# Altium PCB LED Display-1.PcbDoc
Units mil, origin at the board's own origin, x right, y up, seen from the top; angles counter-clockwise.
Board outline 2585 x 1955 mil, 2 copper layers (Top Layer, Bottom Layer); 14 components, 34 nets, 125 pads, 30 vias.
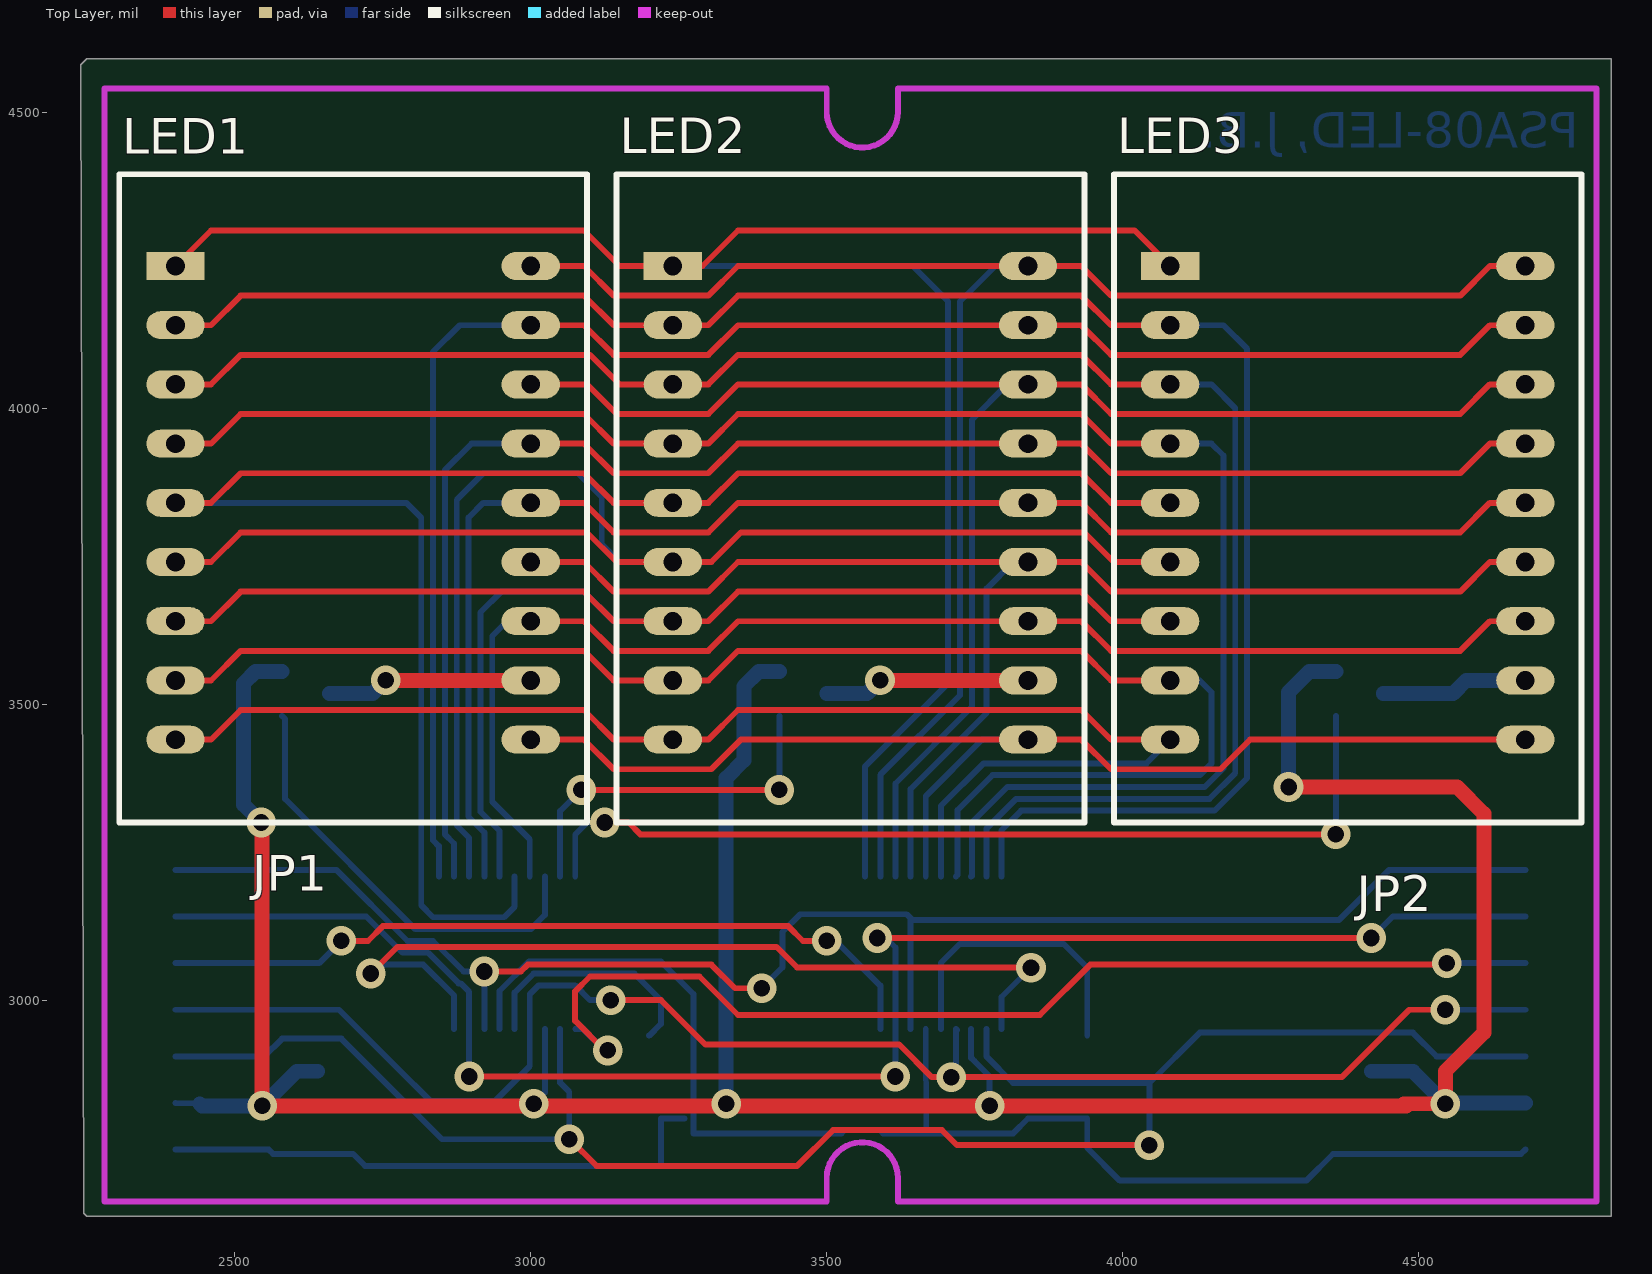
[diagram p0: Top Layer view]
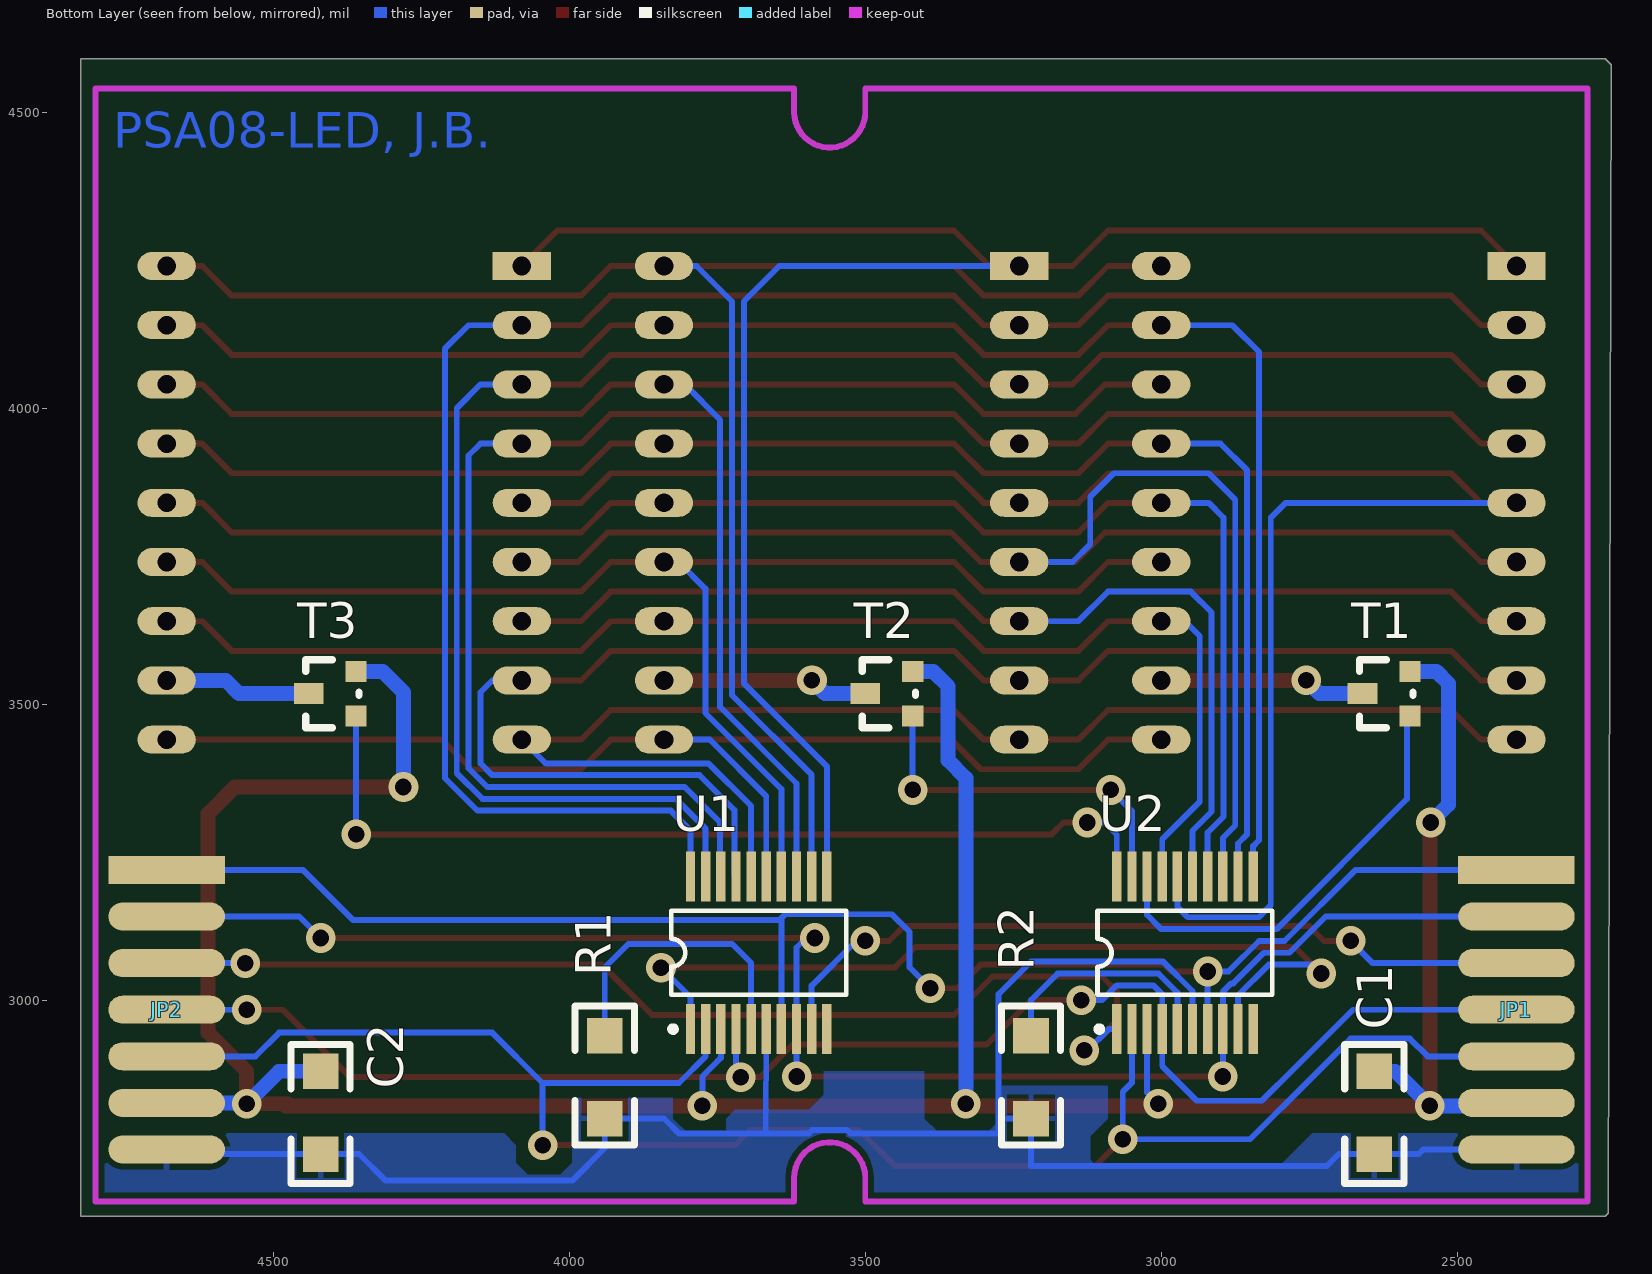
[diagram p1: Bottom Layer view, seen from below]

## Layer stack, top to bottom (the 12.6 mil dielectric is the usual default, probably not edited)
Top Layer: signal copper 1.4
Dielectric: dielectric 12.6, FR-4, Dk 4.8
Bottom Layer: signal copper 1.4

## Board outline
2240,4580 2250,4590 4825,4590 4825,2635 2250,2635 2245,2640

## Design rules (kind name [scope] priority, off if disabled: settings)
Clearance [All] p1: gap=10
PolygonConnect [All] p1: connectstyle=Relief reliefconductorwidth=10 reliefentries=4 polygonreliefangle="90 Angle"
RoutingVias [All] p1: holewidth=28 width=50 viastyle="Through Hole" minholewidth=28 minwidth=50 maxholewidth=28 maxwidth=50
SilkscreenOverComponentPads [All] p1: minsilkscreentomaskgap=10
SolderMaskExpansion [All] p1: expansion=4
Width [All] p1: maxlimit=50 minlimit=10 preferedwidth=10
27 further rules are at their usual default settings.

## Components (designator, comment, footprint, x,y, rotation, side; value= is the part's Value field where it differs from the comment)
C1 "Cap" 1206 2640,2740 r90 bottom
C2 "Cap" 1206 4420,2740 r90 bottom
JP1 "Header 7" ZLACZE-K7 2400,3220 r270 top
JP2 "Header 7" ZLACZE-K7 4680,3220 r270 top
LED1 "PSA11-08GWA" PSA08-11 2400,4240 r0 top
LED2 "PSA11-08GWA" PSA08-11 3240,4240 r0 top
LED3 "PSA11-08GWA" PSA08-11 4080,4240 r0 top
R1 "Res2" 1206 3940,2940 r270 bottom
R2 "Res2" 1206 3220,2940 r270 bottom
T1 "BC858B" SOT-23 2580,3480 r90 bottom
T2 "BC858B" SOT-23 3420,3480 r90 bottom
T3 "BC858B" SOT-23 4360,3480 r90 bottom
U1 "PR4010" SSOP20 3680,3080 r180 bottom
U2 "PR4010" SSOP20 2960,3080 r180 bottom

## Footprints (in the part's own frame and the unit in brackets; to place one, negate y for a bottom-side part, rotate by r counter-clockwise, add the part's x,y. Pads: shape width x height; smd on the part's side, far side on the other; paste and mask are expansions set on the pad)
1206 [mil]
  rect 60x60 smd: 1(0,0) 2(140,0)
  silkscreen extent -50,-50 185,50
PSA08-11 [mm]
  rect 2.5x1.2 hole 0.8: 1(0,0)
  oval 2.5x1.2 hole 0.8: 2(0,-2.54) 3(0,-5.08) 4(0,-7.62) 5(0,-10.16) 6(0,-12.7) 7(0,-15.24) 8(0,-17.78) 9(0,-20.32) 10(15.24,-20.32) 11(15.24,-17.78) 12(15.24,-15.24) 13(15.24,-12.7) 14(15.24,-10.16) 15(15.24,-7.62) 16(15.24,-5.08) 17(15.24,-2.54) 18(15.24,0)
  silkscreen extent -2.41,-23.88 17.65,3.94
SOT-23 [mil]
  rect 36x36 smd: 1(0,0) 2(75,0)
  rect 36x50 smd: 3(38,80)
  silkscreen extent -20,-5 95,85
SSOP20 [mm] "SSOP, Plastic; 20 Leads; Body Width 5.3 mm; Pitch 0.65 mm"
  rect 0.4x2.15 smd: 1(-2.925,-3.275) 2(-2.275,-3.275) 3(-1.625,-3.275) 4(-0.975,-3.275) 5(-0.325,-3.275) 6(0.325,-3.275) 7(0.975,-3.275) 8(1.625,-3.275) 9(2.275,-3.275) 10(2.925,-3.275) 11(2.925,3.275) 12(2.275,3.275) 13(1.625,3.275) 14(0.975,3.275) 15(0.325,3.275) 16(-0.325,3.275) 17(-0.975,3.275) 18(-1.625,3.275) 19(-2.275,3.275) 20(-2.925,3.275)
  silkscreen extent -3.8,-3.4 3.75,1.8
ZLACZE-K7 [mm]
  rect 1.2x5 smd far side: 1(0,0)
  oval 1.2x5 smd far side: 2(2,0) 3(4,0) 4(6,0) 5(8,0) 6(10,0) 7(12,0)

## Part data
C1 C2: "Capacitor"
JP1 JP2: "Header, 7-Pin"
R1 R2: "Resistor"
T1 T2 T3: library part PNP, "PNP Bipolar Transistor"

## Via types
v1: diameter 50, hole 28, Top Layer to Bottom Layer, 30 vias

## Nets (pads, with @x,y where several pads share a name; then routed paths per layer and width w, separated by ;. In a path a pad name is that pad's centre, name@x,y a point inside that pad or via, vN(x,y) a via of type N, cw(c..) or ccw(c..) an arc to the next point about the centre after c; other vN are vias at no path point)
DIG1: T1.1 U2.18 | length 747.1
  Bottom Layer w10: T1.1 2585,3475 2585,3340 2805,3120 3000,3120 3023.98,3143.98 U2.18
DIG2: T2.1 U2.19 | length 620.7
  Top Layer w10: v1(3085,3355) v1(3420,3355)
  Bottom Layer w10: U2.19 3049.57,3319.57 v1(3085,3355) ; v1(3420,3355) T2.1
DIG3: T3.1 U2.20 | length 1572.4
  Top Layer w10: v1(3125,3300) 3165,3300 3185,3280 v1(4360,3280)
  Bottom Layer w10: U2.20 3075.16,3279.84 3095.32,3300 v1(3125,3300) ; v1(4360,3280) T3.1
GND: C1.1 C2.1 JP1.7 JP2.7 R1.2 R2.2 U1.6 U2.6 | length 3312.5
  Bottom Layer w10: JP1.7 2557.44,2747.56 2565,2740 C1.1 2700,2740 2720,2720 3220,2720 R2.2 3260,2800 ; U2.6 2947.2,3015.49 2996.72,3065 3220,3065 3275,3010 3275,2775 3524.78,2775 3530.47,2780.69 3589.53,2780.69 3595.22,2775 3735,2775 3815,2775 3840,2800 R1.2 3940,2750.12 3995.12,2695 4310,2695 4355,2740 4672.44,2740 JP2.7 ; U1.6 3668,2775
NetJP1_1: JP1.1 JP2.1 U1.7 U2.7 | length 2783.4
  Top Layer w10: v1(2921.61,3048.39) 2983.39,3048.39 2995,3060 3305,3060 3345,3020 v1(3390,3020)
  Bottom Layer w10: JP1.1 2671.72,3220 2791.72,3100 2835,3100 2886.61,3048.39 v1(2921.61,3048.39) U2.7 ; v1(3390,3020) 3425,3055 3425,3115 3455,3145 3635,3145 3645,3135 4365,3135 4450,3220 JP2.1 ; U1.7 3641.61,3138.39
NetJP1_2: JP1.2 JP2.2 U1.8 U2.8 | length 2777.3
  Top Layer w10: v1(2896.02,2871.02) v1(3616.02,2871.02) ; v1(3585,3105) v1(4420,3105)
  Bottom Layer w10: JP1.2 2722.17,3141.26 2783.43,3080 2826.72,3080 2878.33,3028.39 2881.61,3028.39 2896.02,3013.98 U2.8 v1(2896.02,2871.02) ; v1(3585,3105) 3600,3105 3616.02,3088.98 U1.8 v1(3616.02,2871.02) ; v1(4420,3105) 4456.26,3141.26 JP2.2
NetJP1_3: JP1.3 U1.9 | length 1331.4
  Top Layer w10: v1(2680,3100) 2725,3100 2750,3125 3330,3125 3435,3125 3460,3100 v1(3500,3100)
  Bottom Layer w10: JP1.3 2642.52,3062.52 v1(2680,3100) ; v1(3500,3100) 3515,3100 3590.43,3024.57 U1.9
NetJP1_4: JP1.4 JP2.4 U1.4 U2.4 | length 2693.9
  Top Layer w10: v1(3135,3000) 3220,3000 3295,2925 3622.2,2925 3677.2,2870 3687.2,2870 v1(3710,2870) 4370,2870 4483.78,2983.78 v1(4545,2983.78)
  Bottom Layer w10: JP1.4 2676.22,2983.78 2775,2885 2830,2830 2940,2830 2998.39,2888.39 U2.4 2998.39,3010.1 3013.28,3025 3075,3025 3100,3000 v1(3135,3000) ; v1(3710,2870) 3718.39,2878.39 U1.4 U1.4@3720,2949.45 ; v1(4545,2983.78) JP2.4
NetJP1_5: JP1.5 JP2.5 U1.2 U2.2 | length 3106.6
  Top Layer w10: v1(3065,2765) 3065.95,2765 3110.95,2720 3450,2720 3510.69,2780.69 3694.31,2780.69 3720,2755 v1(4045,2755)
  Bottom Layer w10: JP1.5 2550.04,2905.04 2580,2935 2680,2935 2745,2870 2850,2765 v1(3065,2765) 3065,2845 3049.57,2860.43 U2.2 ; U1.2 3769.57,2905 3814.57,2860 4045,2860 ; v1(4045,2755) 4045,2860 ; JP2.5 4529.96,2905.04 4490,2945 4130,2945 4045,2860
NetJP2_3: JP2.3 U2.1 | length 1870.5
  Top Layer w10: v1(3130,2915) 3125,2915 3075,2965 3075,3015 3100,3040 3285,3040 3350,2975 3860,2975 3945,3060 v1@4545,3060
  Bottom Layer w10: U2.1 3088.94,2951.06 3125,2915 v1(3130,2915) ; v1(4547.52,3062.52) JP2.3
NetLED1_11: LED1.11 T1.3 | length 349.1
  Top Layer w25: v1(2755,3540) LED1.11
  Bottom Layer w25: T1.3 2733,3518 v1(2755,3540)
NetLED2_11: LED2.11 T2.3 | length 349.1
  Top Layer w25: v1(3590,3540) LED2.11
  Bottom Layer w25: T2.3 3568,3518 v1(3590,3540)
NetLED3_11: LED3.11 T3.3 | length 249.1
  Bottom Layer w25: T3.3 4558,3518 4580,3540 LED3.11
NetR1_1: R1.1 U1.5 | length 503.8
  Bottom Layer w10: U1.5 3692.8,3062.8 3725,3095 3828.43,3095 3861.57,3095 3900,3095 3940,3055 R1.1
NetR2_1: R2.1 U2.5 | length 409.2
  Bottom Layer w10: U2.5 2972.8,3012.8 3005,3045 3175,3045 3220,3000 3220,2960 R2.1@3200,2940
NetU1_1: U1.1 U2.9 | length 1497.8
  Top Layer w10: v1(2730,3045) 2775,3090 3415,3090 3450,3055 v1(3845,3055)
  Bottom Layer w10: v1(2730,3045) 2745,3060 2818.43,3060 2870.43,3008 U2.9 ; U1.1 3795.16,3005.16 v1(3845,3055)
SEG_A: LED1.1 LED2.1 LED3.1 U1.11 | length 3336.7
  Top Layer w10: LED1.1 2460,4300 3090,4300 3150,4240 LED2.1 3290,4240 3350,4300 4020,4300 LED3.1
  Bottom Layer w10: LED2.1@3278.28,4240 LED2.1 3645,4240 3705,4180 3705,3535 3564.84,3394.84 U1.11
SEG_B: LED1.18 LED2.18 LED3.18 U1.12 | length 2929.5
  Top Layer w10: LED1.18 3090,4240 3140,4190 3300,4190 3350,4240 LED2.18 3930,4240 3980,4190 4570,4190 4620,4240 LED3.18
  Bottom Layer w10: U1.12 3590.43,3380.43 3725,3515 3725,4180 3785,4240 LED2.18
SEG_C: LED1.16 LED2.16 LED3.16 U1.13 | length 2707.2
  Top Layer w10: LED1.16 3095,4040 3145,3990 3300,3990 3350,4040 LED2.16 3930,4040 3980,3990 4570,3990 4620,4040 LED3.16
  Bottom Layer w10: U1.13 3616.02,3366.02 3745,3495 3745,3980 3805,4040 LED2.16
SEG_D: LED1.13 LED2.13 LED3.13 U1.14 | length 2390.7
  Top Layer w10: LED1.13 3090,3740 3140,3690 3300,3690 3350,3740 LED2.13 3930,3740 3980,3690 4570,3690 4620,3740 LED3.13
  Bottom Layer w10: U1.14 3641.61,3356.61 3770,3485 3770,3695 3815,3740 LED2.13
SEG_DP: LED1.12 LED2.12 LED3.12 U2.17 | length 2270.5
  Top Layer w10: LED1.12 3090,3640 3140,3590 3300,3590 3350,3640 LED2.12 3930,3640 3980,3590 4570,3590 4620,3640 LED3.12
  Bottom Layer w10: U2.17 2998.39,3271.61 2935,3335 2935,3615 2960,3640 LED1.12
SEG_E: LED1.10 LED2.10 LED3.10 U1.15 | length 2110.8
  Top Layer w10: LED1.10 3090,3440 3140,3390 3305,3390 3355,3440 LED2.10 3930,3440 3980,3390 4165,3390 4215,3440 LED3.10
  Bottom Layer w10: U1.15 3667.2,3293.2 3667.2,3344.62 3761.29,3438.71 3762.58,3440 LED2.10
SEG_F: LED1.9 LED2.9 LED3.9 U1.16 | length 2315.4
  Top Layer w10: LED1.9 2460,3440 2510,3490 3090,3490 3140,3440 LED2.9 3300,3440 3350,3490 3930,3490 3980,3440 LED3.9
  Bottom Layer w10: U1.16 3692.8,3327.8 3765,3400 4040,3400 LED3.9
SEG_G: LED1.8 LED2.8 LED3.8 U1.17 | length 2536
  Top Layer w10: LED1.8 2460,3540 2510,3590 3090,3590 3140,3540 LED2.8 3300,3540 3350,3590 3930,3590 3980,3540 LED3.8
  Bottom Layer w10: U1.17 3721.1,3211.65 3721.1,3321.1 3780,3380 4130,3380 4150,3400 4150,3520 4130,3540 LED3.8
SEG_H: LED1.4 LED2.4 LED3.4 U1.18 | length 2943.9
  Top Layer w10: LED1.4 2460,3940 2510,3990 3090,3990 3140,3940 LED2.4 3300,3940 3350,3990 3930,3990 3980,3940 LED3.4
  Bottom Layer w10: U1.18 3745,3209.96 3745,3300 3805,3360 4138.28,3360 4170,3391.72 4170,3920 4150,3940 LED3.4
SEG_K: LED1.3 LED2.3 LED3.3 U1.19 | length 3045.9
  Top Layer w10: LED1.3 2460,4040 2510,4090 3100,4090 3150,4040 LED2.3 3300,4040 3350,4090 3930,4090 3980,4040 LED3.3
  Bottom Layer w10: U1.19 3769.57,3289.57 3820,3340 4146.57,3340 4190,3383.43 4190,4000 4150,4040 LED3.3
SEG_M: LED1.2 LED2.2 LED3.2 U1.20 | length 3163.6
  Top Layer w10: LED1.2 2460,4140 2510,4190 3090,4190 3140,4140 LED2.2 3300,4140 3350,4190 3930,4190 3980,4140 LED3.2
  Bottom Layer w10: U1.20 3795.16,3286.87 3828.28,3320 4154.85,3320 4210,3375.15 4210,4100 4170,4140 LED3.2
SEG_N: LED1.17 LED2.17 LED3.17 U2.11 | length 2836.6
  Top Layer w10: LED1.17 3090,4140 3140,4090 3300,4090 3350,4140 LED2.17 3930,4140 3980,4090 4570,4090 4620,4140 LED3.17
  Bottom Layer w10: U2.11 2844.84,3260.16 2835,3270 2835,4095 2880,4140 LED1.17
SEG_P: LED1.15 LED2.15 LED3.15 U2.12 | length 2618.9
  Top Layer w10: LED1.15 3090,3940 3140,3890 3300,3890 3350,3940 LED2.15 3930,3940 3980,3890 4570,3890 4620,3940 LED3.15
  Bottom Layer w10: U2.12 2870.43,3264.57 2855,3280 2855,3895 2900,3940 LED1.15
SEG_R: LED1.14 LED2.14 LED3.14 U2.14 | length 2495.3
  Top Layer w10: LED1.14 3090,3840 3140,3790 3300,3790 3350,3840 LED2.14 3930,3840 3980,3790 4570,3790 4620,3840 LED3.14
  Bottom Layer w10: U2.14 2921.61,3283.23 2895,3309.84 2895,3815 2920,3840 LED1.14
SEG_S: LED1.6 LED2.6 LED3.6 U2.13 | length 2900.2
  Top Layer w10: LED1.6 2460,3740 2510,3790 3095,3790 3145,3740 LED2.6 3305,3740 3355,3790 3935,3790 3985,3740 LED3.6
  Bottom Layer w10: U2.13 2896.02,3273.98 2875,3295 2875,3845 2920,3890 3080,3890 3120,3850 3120,3770 3150,3740 LED2.6
SEG_T: LED1.7 LED2.7 LED3.7 U2.15 | length 2582.5
  Top Layer w10: LED1.7 2460,3640 2510,3690 3090,3690 3140,3640 LED2.7 3300,3640 3350,3690 3930,3690 3980,3640 LED3.7
  Bottom Layer w10: U2.15 2947.2,3285.92 2915,3318.13 2915,3655 2950,3690 3090,3690 3140,3640 LED2.7
SEG_U: LED1.5 LED2.5 LED3.5 U2.16 | length 3067.8
  Top Layer w10: LED1.5 2460,3840 2510,3890 3090,3890 3140,3840 LED2.5 3300,3840 3350,3890 3930,3890 3980,3840 LED3.5
  Bottom Layer w10: LED1.5 2790,3840 2815,3815 2815,3160 2835,3140 2955,3140 2972.8,3157.8 U2.16
VCC: C1.2 C2.2 JP1.6 JP2.6 T1.2 T2.2 T3.2 U1.3 U2.3 | length 5537.4
  Top Layer w25: v1@2546.3,3300 v1(2546.3,2821.3) v1(3775,2821.3) 4478.7,2821.3 4475,2825 v1(4545,2825) ; v1(4280,3360) 4565,3360 4610,3315 4610,2945 4545,2880 v1@4545,2826.3
  Bottom Layer w10: JP1.6 2436.57,2825.05 JP1.6@2440.99,2825.05 ; 2605,2880 2608,2880 ; v1(3005,2825) 3023.98,2843.98 U2.3 ; U1.3 3743.98,2902.59 3749.57,2897 ; 3749.42,2896.86 3775,2871.28 v1(3775,2821.3)
  Bottom Layer w25: JP1.6@2440.99,2825.05 2444.74,2821.3 v1(2546.3,2821.3) 2605,2880 ; v1(2545,3300) 2515,3330 2515,3535 2535,3555 T1.2 ; 2608,2880 C1.2 ; v1(3330,2825) 3330,3375 3360,3405 3360,3530 3385,3555 T2.2 ; v1(4280,3360) 4280,3520 4315,3555 T3.2 ; C2.2 4490,2880 v1(4545,2825) ; v1@4546.3,2826.3 JP2.6
pads on no net: U1.10 U2.10

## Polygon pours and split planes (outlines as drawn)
GND on Bottom Layer "Top Layer-No Net" (solid, remove dead copper, pour order 1000): 2295,2775 2295,2670 4790,2670 4790,2765 4790,2775 4540,2775 4110,2775 4090,2755 4090,2725 4070,2705 4015,2705 3995,2725 3995,2830 3995,2835 3865,2835 3825,2835 3825,2800 3800,2775 3660,2775 3295,2775 3270,2800 3270,2855 3090,2855 3090,2800 3120,2770 3120,2765 3120,2730 3110,2720 3090,2720 2800,2720 2745,2775 2295,2775
GND on Bottom Layer "Top Layer-No Net" (solid, remove dead copper, pour order 1001): 3375,2775 3400,2800 3400,2880 3570,2880 3570,2840 3595,2815 3720,2815 3735,2800 3735,2775 3375,2775

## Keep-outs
Keep-Out Layer:
  lines w10: 2280,2660 3500,2660 3500,2700 cw(c3560,2700) 3620,2700 3620,2660 4800,2660 4800,4500 4800,4540 3620,4540 3620,4500 cw(c3560,4500) 3500,4500 3500,4540 2280,4540 2280,2720 2280,2660

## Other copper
Bottom Layer:
  text "PSA08-LED, J.B." at 4770,4440 h60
